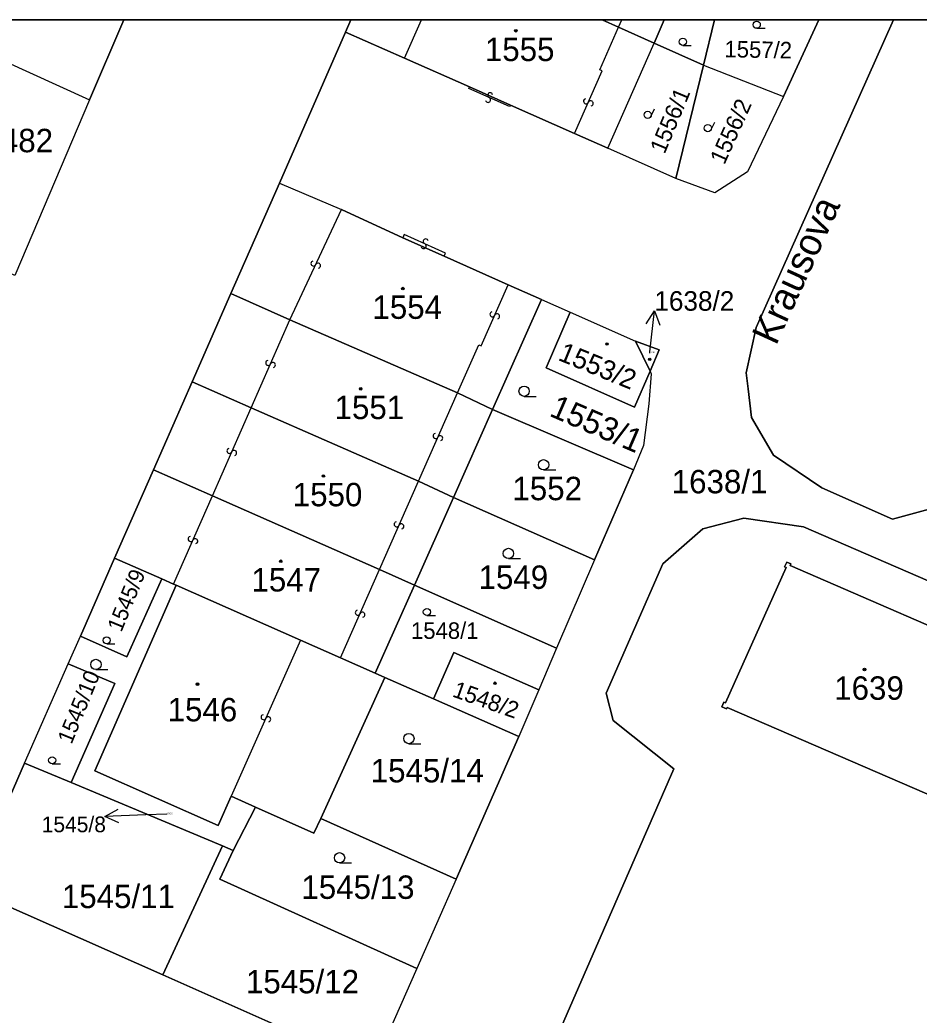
# Model space of a CAD drawing. Extents: x -596024 to -594475, y -1163820 to -1161957.
# Drawn here: x -595817.6 to -595752.3, y -1162029.1 to -1161956.9 of the extents above; entities that cross this region are included whole.
import ezdxf

# ---------------------------------------------------------------- set-up
doc = ezdxf.new("R2010")
doc.units = 0
for name, color, linetype in [('Level 1', 7, 'Continuous'), ('Level 11', 7, 'Continuous'), ('Level 13', 7, 'Continuous'), ('Level 3', 7, 'Continuous'), ('Level 4', 7, 'Continuous'), ('Level 5', 7, 'Continuous'), ('Level 57', 7, 'Continuous'), ('Level 60', 7, 'Continuous'), ('Vrstva 60', 7, 'Continuous'), ('Vrstva 63', 7, 'Continuous')]:
    doc.layers.add(name, color=color, linetype=linetype)

msp = doc.modelspace()

# ---------------------------------------------------------------- linework, layer by layer
at = {"layer": 'Level 1'}
for p, q in [((-595812.55, -1161962.68), (-595810.061, -1161956.88)), ((-595793.572, -1161956.88), (-595793.96, -1161957.76)), ((-595774.12, -1161957.41), (-595775.32, -1161956.88)), ((-595771.54, -1161958.56), (-595770.804, -1161956.88)), ((-595767.95, -1161960.16), (-595767.156, -1161956.88)), ((-595762.13, -1161962.45), (-595759.571, -1161956.88))]:
    msp.add_line(p, q, dxfattribs=at)
for points in [[(-595717.56, -1162012.36), (-595716.25, -1162009.58), (-595728.93, -1162004.09), (-595730, -1162000.43), (-595731.67, -1161998.72), (-595748.51, -1161991.59), (-595754.22, -1161993.13), (-595759.35, -1161990.85), (-595762.87, -1161988.5), (-595764.46, -1161985.75), (-595764.69, -1161983.67), (-595764.84, -1161982.52), (-595764.11, -1161979.22), (-595754.128, -1161956.88)], [(-595793.96, -1161957.76), (-595798.76, -1161968.73)], [(-595793.96, -1161957.76), (-595789.66, -1161959.66)], [(-595771.54, -1161958.56), (-595774.12, -1161957.41)], [(-595821.03, -1161958.83), (-595812.55, -1161962.68)], [(-595774.89, -1161966.2), (-595771.54, -1161958.56)], [(-595767.95, -1161960.16), (-595771.54, -1161958.56)], [(-595789.66, -1161959.66), (-595784.95, -1161961.75)], [(-595769.95, -1161968.39), (-595767.95, -1161960.16)], [(-595767.95, -1161960.16), (-595762.13, -1161962.45)], [(-595784.95, -1161961.75), (-595781.98, -1161963.06)], [(-595812.55, -1161962.68), (-595817.98, -1161975.44)], [(-595762.13, -1161962.45), (-595764.74, -1161967.92), (-595767.11, -1161969.44), (-595769.95, -1161968.39)], [(-595781.98, -1161963.06), (-595777.31, -1161965.13)], [(-595777.31, -1161965.13), (-595774.89, -1161966.2)], [(-595769.95, -1161968.39), (-595774.89, -1161966.2)], [(-595798.76, -1161968.73), (-595802.28, -1161976.75)], [(-595798.76, -1161968.73), (-595794.25, -1161970.65)], [(-595789.8, -1161972.7), (-595794.25, -1161970.65)], [(-595786.79, -1161974.04), (-595789.8, -1161972.7)], [(-595782.13, -1161976.11), (-595786.79, -1161974.04)], [(-595779.72, -1161977.18), (-595782.13, -1161976.11)], [(-595802.28, -1161976.75), (-595805.1, -1161983.16)], [(-595802.28, -1161976.75), (-595797.99, -1161978.65)], [(-595783.27, -1161985.18), (-595779.72, -1161977.18)], [(-595779.72, -1161977.18), (-595777.64, -1161978.1)], [(-595797.99, -1161978.65), (-595785.82, -1161983.97)], [(-595777.64, -1161978.1), (-595779.38, -1161982.14), (-595772.97, -1161985), (-595771.83, -1161982.39)], [(-595777.64, -1161978.1), (-595772.88, -1161980.21)], [(-595772.88, -1161980.21), (-595771.83, -1161982.39)], [(-595771.83, -1161982.39), (-595771.16, -1161980.85), (-595772.88, -1161980.21)], [(-595771.83, -1161982.39), (-595771.74, -1161982.57), (-595771.91, -1161984.75), (-595772.3, -1161987.79), (-595773.02, -1161989.55)], [(-595805.1, -1161983.16), (-595807.91, -1161989.56)], [(-595805.1, -1161983.16), (-595800.81, -1161985.06)], [(-595785.82, -1161983.97), (-595783.27, -1161985.18)], [(-595800.81, -1161985.06), (-595788.65, -1161990.38)], [(-595786.11, -1161991.56), (-595783.27, -1161985.18)], [(-595783.27, -1161985.18), (-595773.02, -1161989.55)], [(-595807.91, -1161989.56), (-595810.73, -1161995.97)], [(-595803.63, -1161991.45), (-595807.91, -1161989.56)], [(-595775.86, -1161996.09), (-595773.02, -1161989.55)], [(-595788.65, -1161990.38), (-595786.11, -1161991.56)], [(-595791.49, -1161996.8), (-595803.63, -1161991.45)], [(-595788.95, -1161997.94), (-595786.11, -1161991.56)], [(-595786.11, -1161991.56), (-595775.86, -1161996.09)], [(-595717.56, -1162012.36), (-595760.69, -1161993.7), (-595765.02, -1161993.06), (-595768, -1161993.84), (-595770.9, -1161996.37), (-595775.01, -1162005.78), (-595774.51, -1162007.75), (-595770.09, -1162011.27), (-595780.91, -1162036.02), (-595772.86, -1162039.04), (-595767.5, -1162038.51), (-595766.05, -1162038.33), (-595751.36, -1162044.82), (-595750.56, -1162046.25), (-595751.09, -1162048.41), (-595750.09, -1162049.69), (-595736.17, -1162055.68), (-595737.31, -1162058.36)], [(-595810.73, -1161995.97), (-595813.22, -1162001.63)], [(-595810.73, -1161995.97), (-595807.31, -1161997.48)], [(-595788.95, -1161997.94), (-595791.49, -1161996.8)], [(-595775.86, -1161996.09), (-595778.62, -1162002.51)], [(-595745.35, -1162003.57), (-595761.65, -1161996.5), (-595761.61, -1161996.39), (-595761.9, -1161996.26), (-595762.05, -1161996.6), (-595761.94, -1161996.65), (-595766.35, -1162006.48), (-595766.46, -1162006.43), (-595766.61, -1162006.77), (-595766.27, -1162006.92), (-595766.22, -1162006.81), (-595749.93, -1162013.86)], [(-595813.22, -1162001.63), (-595809.85, -1162003.14), (-595807.31, -1161997.48)], [(-595807.31, -1161997.48), (-595806.45, -1161997.86)], [(-595806.26, -1161997.94), (-595812.17, -1162011.4), (-595803.22, -1162015.37), (-595802.27, -1162013.25)], [(-595806.45, -1161997.86), (-595806.26, -1161997.94)], [(-595806.26, -1161997.94), (-595797.22, -1162001.93)], [(-595791.79, -1162004.33), (-595788.95, -1161997.94)], [(-595778.62, -1162002.51), (-595788.95, -1161997.94)], [(-595814.1, -1162003.63), (-595813.22, -1162001.63)], [(-595797.22, -1162001.93), (-595794.32, -1162003.21)], [(-595778.62, -1162002.51), (-595779.91, -1162005.52)], [(-595794.32, -1162003.21), (-595791.79, -1162004.33)], [(-595779.91, -1162005.52), (-595786.08, -1162002.82), (-595787.57, -1162006.19)], [(-595817.27, -1162010.85), (-595814.1, -1162003.63)], [(-595814.1, -1162003.63), (-595810.71, -1162005.07), (-595813.88, -1162012.26)], [(-595795.76, -1162014.87), (-595791.09, -1162004.64)], [(-595791.79, -1162004.33), (-595791.09, -1162004.64)], [(-595791.09, -1162004.64), (-595787.57, -1162006.19)], [(-595787.57, -1162006.19), (-595781.37, -1162008.93)], [(-595779.91, -1162005.52), (-595781.37, -1162008.93)], [(-595785.92, -1162019.28), (-595781.37, -1162008.93)], [(-595817.27, -1162010.85), (-595820.19, -1162017.48), (-595821.3, -1162020)], [(-595813.88, -1162012.26), (-595817.27, -1162010.85)], [(-595813.88, -1162012.26), (-595802.89, -1162016.86)], [(-595800.49, -1162014.05), (-595802.27, -1162013.25)], [(-595802.11, -1162017.2), (-595800.49, -1162014.05)], [(-595795.76, -1162014.87), (-595796.25, -1162015.94), (-595800.49, -1162014.05)], [(-595785.92, -1162019.28), (-595795.76, -1162014.87)], [(-595802.89, -1162016.86), (-595807.23, -1162026.23)], [(-595802.89, -1162016.86), (-595802.11, -1162017.2)], [(-595802.11, -1162017.2), (-595803.08, -1162019.28), (-595788.77, -1162025.76)], [(-595785.92, -1162019.28), (-595788.77, -1162025.76)], [(-595807.23, -1162026.23), (-595821.3, -1162020)], [(-595807.23, -1162026.23), (-595791.96, -1162033)], [(-595788.77, -1162025.76), (-595791.96, -1162033)]]:
    msp.add_lwpolyline(points, dxfattribs=at)
at = {"layer": 'Level 13'}
for centre, start, end in [((-595783.596, -1161962.688), 193.57154, 65.66954), ((-595783.445, -1161962.352), 13.35708, 245.94708), ((-595776.478, -1161962.784), 103.53889, 335.63689), ((-595776.142, -1161962.935), 283.32444, 155.91444), ((-595788.124, -1161972.972), 13.16048, 245.75048), ((-595788.277, -1161973.308), 193.37493, 65.47293), ((-595796.286, -1161974.57), 102.31664, 334.41464), ((-595795.954, -1161974.729), 282.10219, 154.69219), ((-595783.278, -1161978.254), 103.55408, 335.65208), ((-595782.942, -1161978.405), 283.33963, 155.92963), ((-595799.568, -1161981.784), 103.62623, 335.72423), ((-595799.232, -1161981.935), 283.41178, 156.00178), ((-595787.408, -1161987.104), 103.55139, 335.64938), ((-595787.072, -1161987.255), 283.33693, 155.92693), ((-595802.388, -1161988.174), 103.56017, 335.65816), ((-595802.052, -1161988.325), 283.34571, 155.93571), ((-595790.238, -1161993.514), 103.50969, 335.60768), ((-595789.902, -1161993.665), 283.29523, 155.88523), ((-595805.208, -1161994.584), 103.62623, 335.72423), ((-595804.872, -1161994.735), 283.41178, 156.00178), ((-595793.068, -1161999.924), 103.55139, 335.64938), ((-595792.732, -1162000.075), 283.33693, 155.92693), ((-595799.908, -1162007.514), 103.116, 335.706), ((-595799.572, -1162007.667), 283.33046, 155.42846)]:
    msp.add_arc(centre, 0.184, start, end, dxfattribs=at)
at = {"layer": 'Level 3'}
for p, q in [((-595789.66, -1161959.66), (-595788.427, -1161956.88)), ((-595774.12, -1161957.41), (-595773.886, -1161956.88))]:
    msp.add_line(p, q, dxfattribs=at)
for points in [[(-595777.31, -1161965.13), (-595775.3, -1161960.58), (-595775.48, -1161960.5), (-595774.12, -1161957.41)], [(-595781.98, -1161963.06), (-595782.03, -1161963.17), (-595785, -1161961.86), (-595784.95, -1161961.75)], [(-595797.99, -1161978.65), (-595794.25, -1161970.65)], [(-595786.79, -1161974.04), (-595786.69, -1161973.81), (-595789.7, -1161972.47), (-595789.8, -1161972.7)], [(-595785.82, -1161983.97), (-595784.28, -1161980.47), (-595784.09, -1161980.55), (-595782.13, -1161976.11)], [(-595800.81, -1161985.06), (-595797.99, -1161978.65)], [(-595788.65, -1161990.38), (-595785.82, -1161983.97)], [(-595803.63, -1161991.45), (-595800.81, -1161985.06)], [(-595791.49, -1161996.8), (-595788.65, -1161990.38)], [(-595806.45, -1161997.86), (-595803.63, -1161991.45)], [(-595794.32, -1162003.21), (-595791.49, -1161996.8)], [(-595797.22, -1162001.93), (-595802.27, -1162013.25)]]:
    msp.add_lwpolyline(points, dxfattribs=at)
at = {"layer": 'Level 5'}
for p, q in [((-595764.08, -1161957.49), (-595763.468, -1161957.49)), ((-595769.45, -1161958.73), (-595768.838, -1161958.73)), ((-595771.76, -1161963.89), (-595771.5, -1161963.335)), ((-595767.39, -1161964.85), (-595767.127, -1161964.297)), ((-595780.98, -1161984.22), (-595780.105, -1161984.22)), ((-595779.56, -1161989.56), (-595778.685, -1161989.56)), ((-595782.12, -1161996), (-595781.245, -1161996)), ((-595788.04, -1162000.14), (-595787.428, -1162000.14)), ((-595811.31, -1162002.19), (-595810.715, -1162002.19)), ((-595812.09, -1162004.06), (-595811.215, -1162004.06)), ((-595789.35, -1162009.44), (-595788.475, -1162009.44)), ((-595815.27, -1162010.9), (-595814.675, -1162010.9)), ((-595794.39, -1162018.1), (-595793.515, -1162018.1))]:
    msp.add_line(p, q, dxfattribs=at)
for centre, radius in [((-595764.08, -1161957.227), 0.262), ((-595781.58, -1161957.67), 0.09), ((-595781.58, -1161957.67), 0.0521), ((-595769.45, -1161958.467), 0.262), ((-595771.998, -1161963.779), 0.262), ((-595767.627, -1161964.737), 0.262), ((-595789.79, -1161976.39), 0.09), ((-595789.79, -1161976.39), 0.0521), ((-595774.95, -1161980.42), 0.09), ((-595774.95, -1161980.42), 0.0521), ((-595771.85, -1161981.53), 0.09), ((-595771.85, -1161981.53), 0.0521), ((-595792.85, -1161983.67), 0.09), ((-595792.85, -1161983.67), 0.0521), ((-595780.98, -1161983.845), 0.375), ((-595779.56, -1161989.185), 0.375), ((-595795.56, -1161990), 0.09), ((-595795.56, -1161990), 0.0521), ((-595782.12, -1161995.625), 0.375), ((-595798.66, -1161996.19), 0.09), ((-595798.66, -1161996.19), 0.0521), ((-595788.04, -1161999.877), 0.262), ((-595811.31, -1162001.935), 0.255), ((-595812.09, -1162003.685), 0.375), ((-595756.25, -1162004.05), 0.09), ((-595756.25, -1162004.05), 0.0521), ((-595804.71, -1162005.12), 0.09), ((-595804.71, -1162005.12), 0.0521), ((-595783.1, -1162005.05), 0.09), ((-595783.1, -1162005.05), 0.0521), ((-595789.35, -1162009.065), 0.375), ((-595815.27, -1162010.645), 0.255), ((-595794.39, -1162017.725), 0.375)]:
    msp.add_circle(centre, radius, dxfattribs=at)
at = {"layer": 'Level 57'}
for p, q in [((-595771.84, -1161980.982), (-595771.516, -1161978)), ((-595771.85, -1161981.07), (-595771.84, -1161980.982)), ((-595808.455, -1162014.617), (-595811.453, -1162014.73)), ((-595806.95, -1162014.56), (-595808.455, -1162014.617))]:
    msp.add_line(p, q, dxfattribs=at)
for points in [[(-595772.121, -1161978.94), (-595771.516, -1161978), (-595771.127, -1161979.048)], [(-595810.435, -1162015.192), (-595811.453, -1162014.73), (-595810.472, -1162014.193)]]:
    msp.add_lwpolyline(points, dxfattribs=at)
at = {"layer": 'Level 60'}
for points in [[(-595812.55, -1161962.68), (-595817.98, -1161975.44), (-595822.86, -1161973.2), (-595826.57, -1161971.49), (-595825.18, -1161968.14), (-595824.5, -1161966.77), (-595821.03, -1161958.83)], [(-595767.95, -1161960.16), (-595769.95, -1161968.39), (-595774.89, -1161966.2), (-595771.54, -1161958.56)], [(-595769.95, -1161968.39), (-595767.95, -1161960.16), (-595762.13, -1161962.45), (-595764.74, -1161967.92), (-595767.11, -1161969.44)], [(-595802.28, -1161976.75), (-595798.76, -1161968.73), (-595794.25, -1161970.65), (-595789.8, -1161972.7), (-595786.79, -1161974.04), (-595782.13, -1161976.11), (-595779.72, -1161977.18), (-595783.27, -1161985.18), (-595785.82, -1161983.97), (-595797.99, -1161978.65)], [(-595805.1, -1161983.16), (-595802.28, -1161976.75), (-595797.99, -1161978.65), (-595785.82, -1161983.97), (-595783.27, -1161985.18), (-595786.11, -1161991.56), (-595788.65, -1161990.38), (-595800.81, -1161985.06)], [(-595771.83, -1161982.39), (-595771.74, -1161982.57), (-595771.91, -1161984.75), (-595772.3, -1161987.79), (-595773.02, -1161989.55), (-595783.27, -1161985.18), (-595779.72, -1161977.18), (-595777.64, -1161978.1), (-595779.38, -1161982.14), (-595772.97, -1161985)], [(-595772.88, -1161980.21), (-595771.83, -1161982.39), (-595772.97, -1161985), (-595779.38, -1161982.14), (-595777.64, -1161978.1)], [(-595771.83, -1161982.39), (-595772.88, -1161980.21), (-595771.16, -1161980.85)], [(-595807.91, -1161989.56), (-595805.1, -1161983.16), (-595800.81, -1161985.06), (-595788.65, -1161990.38), (-595786.11, -1161991.56), (-595788.95, -1161997.94), (-595791.49, -1161996.8), (-595803.63, -1161991.45)], [(-595786.11, -1161991.56), (-595783.27, -1161985.18), (-595773.02, -1161989.55), (-595775.86, -1161996.09)], [(-595810.73, -1161995.97), (-595807.91, -1161989.56), (-595803.63, -1161991.45), (-595791.49, -1161996.8), (-595788.95, -1161997.94), (-595791.79, -1162004.33), (-595794.32, -1162003.21), (-595797.22, -1162001.93), (-595806.26, -1161997.94), (-595806.45, -1161997.86), (-595807.31, -1161997.48)], [(-595788.95, -1161997.94), (-595786.11, -1161991.56), (-595775.86, -1161996.09), (-595778.62, -1162002.51)], [(-595726.38, -1162054.37), (-595727.2, -1162060.36), (-595727.24, -1162062.63), (-595737.31, -1162058.36), (-595736.17, -1162055.68), (-595750.09, -1162049.69), (-595751.09, -1162048.41), (-595750.56, -1162046.25), (-595751.36, -1162044.82), (-595766.05, -1162038.33), (-595767.5, -1162038.51), (-595772.86, -1162039.04), (-595780.91, -1162036.02), (-595770.09, -1162011.27), (-595774.51, -1162007.75), (-595775.01, -1162005.78), (-595770.9, -1161996.37), (-595768, -1161993.84), (-595765.02, -1161993.06), (-595760.69, -1161993.7), (-595717.56, -1162012.36), (-595709.71, -1162015.74), (-595716.25, -1162030.74)], [(-595813.22, -1162001.63), (-595810.73, -1161995.97), (-595807.31, -1161997.48), (-595809.85, -1162003.14)], [(-595711.98, -1162017.91), (-595712.27, -1162017.78), (-595712.32, -1162017.89), (-595728.69, -1162010.79), (-595745.35, -1162003.57), (-595761.65, -1161996.5), (-595761.61, -1161996.39), (-595761.9, -1161996.26), (-595762.05, -1161996.6), (-595761.94, -1161996.65), (-595766.35, -1162006.48), (-595766.46, -1162006.43), (-595766.61, -1162006.77), (-595766.27, -1162006.92), (-595766.22, -1162006.81), (-595749.93, -1162013.86), (-595733.22, -1162021.1), (-595716.82, -1162028.2), (-595716.86, -1162028.31), (-595716.57, -1162028.44), (-595716.44, -1162028.15), (-595716.55, -1162028.1), (-595712.22, -1162018.15), (-595712.11, -1162018.2)], [(-595761.61, -1161996.39), (-595761.65, -1161996.5), (-595745.35, -1162003.57), (-595749.93, -1162013.86), (-595766.22, -1162006.81), (-595766.27, -1162006.92), (-595766.61, -1162006.77), (-595766.46, -1162006.43), (-595766.35, -1162006.48), (-595761.94, -1161996.65), (-595762.05, -1161996.6), (-595761.9, -1161996.26)], [(-595810.71, -1162005.07), (-595814.1, -1162003.63), (-595813.22, -1162001.63), (-595809.85, -1162003.14), (-595807.31, -1161997.48), (-595806.45, -1161997.86), (-595806.26, -1161997.94), (-595812.17, -1162011.4), (-595803.22, -1162015.37), (-595802.27, -1162013.25), (-595800.49, -1162014.05), (-595802.11, -1162017.2), (-595802.89, -1162016.86), (-595813.88, -1162012.26)], [(-595794.32, -1162003.21), (-595791.79, -1162004.33), (-595791.09, -1162004.64), (-595795.76, -1162014.87), (-595796.25, -1162015.94), (-595800.49, -1162014.05), (-595802.27, -1162013.25), (-595803.22, -1162015.37), (-595812.17, -1162011.4), (-595806.26, -1161997.94), (-595797.22, -1162001.93)], [(-595791.79, -1162004.33), (-595788.95, -1161997.94), (-595778.62, -1162002.51), (-595779.91, -1162005.52), (-595786.08, -1162002.82), (-595787.57, -1162006.19), (-595791.09, -1162004.64)], [(-595786.08, -1162002.82), (-595779.91, -1162005.52), (-595781.37, -1162008.93), (-595787.57, -1162006.19)], [(-595814.1, -1162003.63), (-595810.71, -1162005.07), (-595813.88, -1162012.26), (-595817.27, -1162010.85)], [(-595795.76, -1162014.87), (-595791.09, -1162004.64), (-595787.57, -1162006.19), (-595781.37, -1162008.93), (-595785.92, -1162019.28)], [(-595813.88, -1162012.26), (-595802.89, -1162016.86), (-595807.23, -1162026.23), (-595821.3, -1162020), (-595820.19, -1162017.48), (-595817.27, -1162010.85)], [(-595802.11, -1162017.2), (-595800.49, -1162014.05), (-595796.25, -1162015.94), (-595795.76, -1162014.87), (-595785.92, -1162019.28), (-595788.77, -1162025.76), (-595803.08, -1162019.28)], [(-595807.23, -1162026.23), (-595802.89, -1162016.86), (-595802.11, -1162017.2), (-595803.08, -1162019.28), (-595788.77, -1162025.76), (-595791.96, -1162033)], [(-595846.14, -1162076.49), (-595843.91, -1162071.39), (-595836.7, -1162054.99), (-595828.92, -1162037.28), (-595824.62, -1162027.54), (-595821.3, -1162020), (-595807.23, -1162026.23), (-595791.96, -1162033), (-595811.08, -1162076.86), (-595812.97, -1162081.62), (-595837.27, -1162083.34), (-595841.15, -1162083.54), (-595842.68, -1162083.1), (-595844.37, -1162082.03), (-595845.54, -1162080.41), (-595846.12, -1162078.49)]]:
    msp.add_lwpolyline(points, close=True, dxfattribs=at)
at = {"layer": 'Vrstva 60'}
for points in [[(-595810.061, -1161956.88), (-595825.407, -1161956.88), (-595821.03, -1161958.83), (-595812.55, -1161962.68)], [(-595775.32, -1161956.88), (-595793.572, -1161956.88), (-595793.96, -1161957.76), (-595789.66, -1161959.66), (-595784.95, -1161961.75), (-595781.98, -1161963.06), (-595777.31, -1161965.13), (-595774.89, -1161966.2), (-595771.54, -1161958.56), (-595774.12, -1161957.41)], [(-595770.804, -1161956.88), (-595775.32, -1161956.88), (-595774.12, -1161957.41), (-595771.54, -1161958.56)], [(-595767.156, -1161956.88), (-595770.804, -1161956.88), (-595771.54, -1161958.56), (-595767.95, -1161960.16)], [(-595759.571, -1161956.88), (-595767.156, -1161956.88), (-595767.95, -1161960.16), (-595762.13, -1161962.45)]]:
    msp.add_lwpolyline(points, close=True, dxfattribs=at)
for points in [[(-595820.19, -1162017.48), (-595817.27, -1162010.85), (-595814.1, -1162003.63), (-595813.22, -1162001.63), (-595810.73, -1161995.97), (-595807.91, -1161989.56), (-595805.1, -1161983.16), (-595802.28, -1161976.75), (-595798.76, -1161968.73), (-595793.96, -1161957.76), (-595793.572, -1161956.88), (-595810.061, -1161956.88), (-595812.55, -1161962.68), (-595817.98, -1161975.44)], [(-595748.51, -1161991.59), (-595754.22, -1161993.13), (-595759.35, -1161990.85), (-595762.87, -1161988.5), (-595764.46, -1161985.75), (-595764.69, -1161983.67), (-595764.84, -1161982.52), (-595764.11, -1161979.22), (-595754.128, -1161956.88), (-595759.571, -1161956.88), (-595762.13, -1161962.45), (-595764.74, -1161967.92), (-595767.11, -1161969.44), (-595769.95, -1161968.39), (-595774.89, -1161966.2), (-595777.31, -1161965.13), (-595781.98, -1161963.06), (-595784.95, -1161961.75), (-595789.66, -1161959.66), (-595793.96, -1161957.76), (-595798.76, -1161968.73), (-595794.25, -1161970.65), (-595789.8, -1161972.7), (-595786.79, -1161974.04), (-595782.13, -1161976.11), (-595779.72, -1161977.18), (-595777.64, -1161978.1), (-595772.88, -1161980.21), (-595771.16, -1161980.85), (-595771.83, -1161982.39), (-595771.74, -1161982.57), (-595771.91, -1161984.75), (-595772.3, -1161987.79), (-595773.02, -1161989.55), (-595775.86, -1161996.09), (-595778.62, -1162002.51), (-595779.91, -1162005.52), (-595781.37, -1162008.93), (-595785.92, -1162019.28), (-595788.77, -1162025.76), (-595791.96, -1162033)], [(-595744.688, -1161956.88), (-595754.128, -1161956.88), (-595764.11, -1161979.22), (-595764.84, -1161982.52), (-595764.69, -1161983.67), (-595764.46, -1161985.75), (-595762.87, -1161988.5), (-595759.35, -1161990.85), (-595754.22, -1161993.13), (-595748.51, -1161991.59)], [(-595780.91, -1162036.02), (-595770.09, -1162011.27), (-595774.51, -1162007.75), (-595775.01, -1162005.78), (-595770.9, -1161996.37), (-595768, -1161993.84), (-595765.02, -1161993.06), (-595760.69, -1161993.7), (-595717.56, -1162012.36)]]:
    msp.add_lwpolyline(points, dxfattribs=at)
at = {"layer": 'Vrstva 63'}
msp.add_lwpolyline([(-594475.47, -1163820.23), (-596024.42, -1163820.23), (-596024.42, -1161956.88), (-594475.47, -1161956.88)], close=True, dxfattribs=at)

# ---------------------------------------------------------------- texts
at = {"layer": 'Level 11'}
msp.add_text('Krausova', height=2, rotation=65.38446, dxfattribs=at).set_placement((-595762.677, -1161980.584))
at = {"layer": 'Level 4'}
for s, height, p in [('1555', 1.7, (-595783.83, -1161959.87)), ('1482', 1.7, (-595820.26, -1161966.49)), ('1554', 1.7, (-595792, -1161978.59)), ('1638/2', 0.1, (-595771.85, -1161981.07)), ('1551', 1.7, (-595794.75, -1161985.87)), ('1638/1', 1.7, (-595770.254, -1161991.26)), ('1552', 1.7, (-595781.83, -1161991.76)), ('1550', 1.7, (-595797.79, -1161992.2)), ('1547', 1.7, (-595800.79, -1161998.39)), ('1549', 1.7, (-595784.29, -1161998.2)), ('1548/1', 1.2, (-595789.2, -1162001.83)), ('1639', 1.7, (-595758.45, -1162006.25)), ('1546', 1.7, (-595806.88, -1162007.82)), ('1545/14', 1.7, (-595792.124, -1162012.25)), ('1545/8', 0.1, (-595806.95, -1162014.56)), ('1545/13', 1.7, (-595797.161, -1162020.71)), ('1545/11', 1.7, (-595814.567, -1162021.38)), ('1545/12', 1.7, (-595801.189, -1162027.57))]:
    msp.add_text(s, height=height, dxfattribs=at).set_placement(p)
for s, height, rotation, p in [('1557/2', 1.2, 358.89201, (-595766.43, -1161959.59)), ('1556/1', 1.2, 67.33116, (-595770.77, -1161966.67)), ('1556/2', 1.2, 65.71422, (-595766.43, -1161967.45)), ('1553/2', 1.42, 337.76982, (-595778.584, -1161981.56)), ('1553/1', 1.7, 336.67434, (-595779.223, -1161985.61)), ('1545/9', 1.14, 67.62816, (-595810.246, -1162001.394)), ('1545/10', 1.14, 67.72266, (-595813.865, -1162009.536)), ('1548/2', 1.2, 340.50105, (-595786.26, -1162006))]:
    msp.add_text(s, height=height, rotation=rotation, dxfattribs=at).set_placement(p)
at = {"layer": 'Level 57'}
for s, height, p in [('1638/2', 1.42, (-595771.516, -1161978)), ('1545/8', 1.14, (-595816.027, -1162015.87))]:
    msp.add_text(s, height=height, dxfattribs=at).set_placement(p)

doc.saveas('drawing.dxf')
